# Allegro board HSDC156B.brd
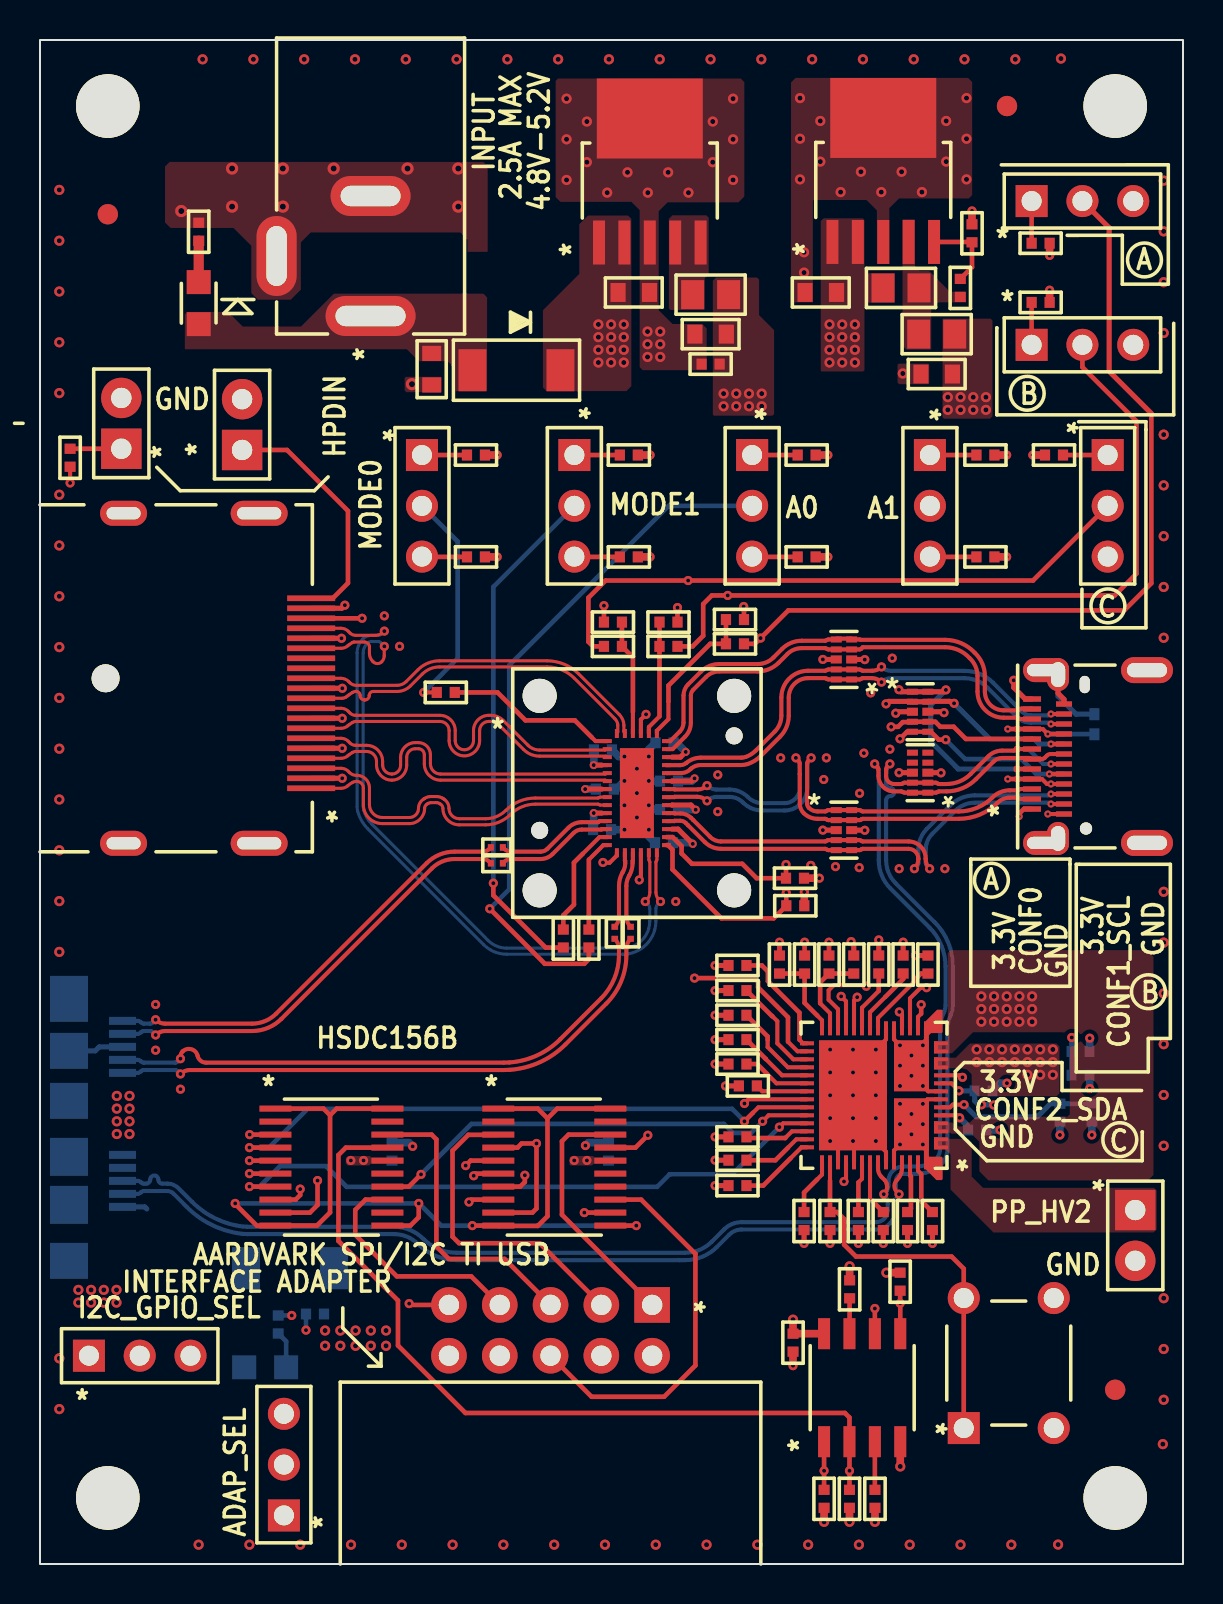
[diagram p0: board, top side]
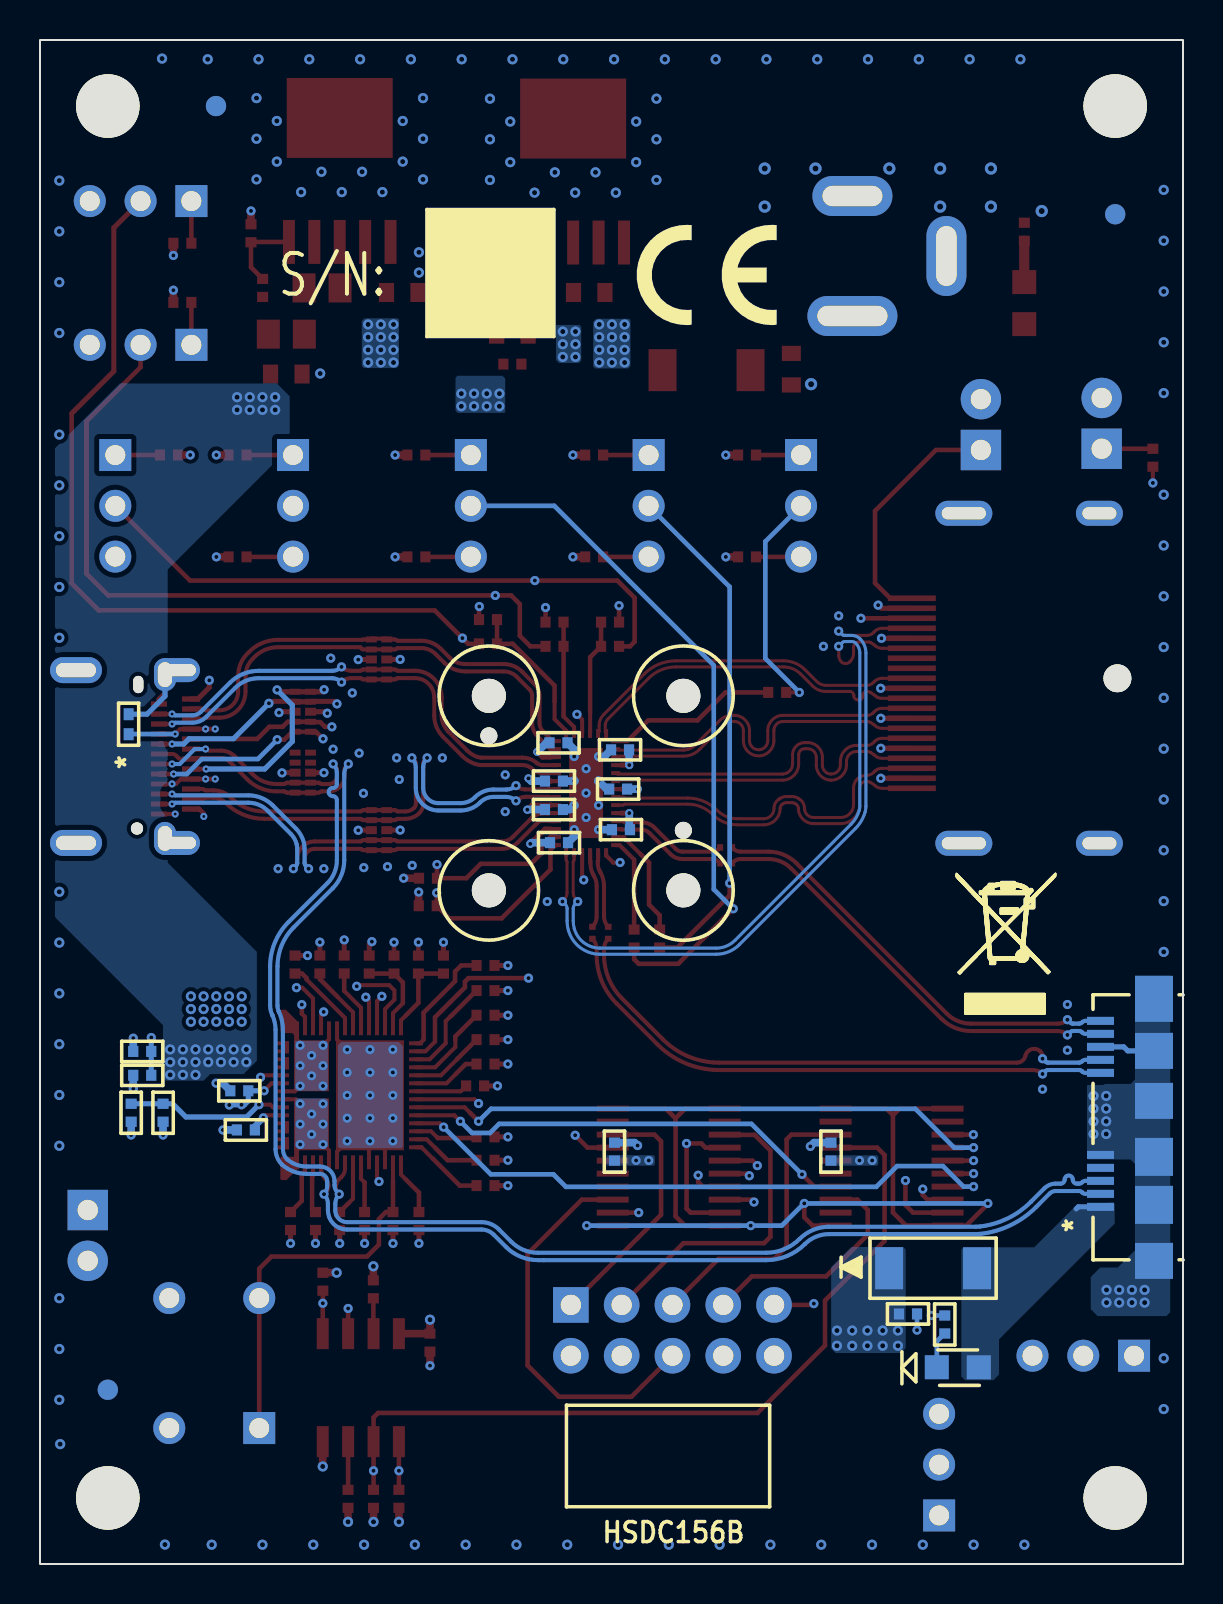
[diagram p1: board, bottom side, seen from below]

Outline 57.16 x 76.2 mm; copper layers: TOP, L2_GND, L3_PWR, L4_SIG, L5_GND, BOTTOM. Coordinates in mm from the lower left corner of the outline.
Outline path: rectangle 0,0 57.16,76.2

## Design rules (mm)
constraint set DEFAULT: min track width 0.229
net group AUX: nets AUXN AUXP
net group SSRXN: nets N16876304 SSRXN
net group SSRXP: nets N16876297 SSRXP
net group SSTXN: nets N16876344 SSTXN
net group SSTXP: nets N16876335 SSTXP

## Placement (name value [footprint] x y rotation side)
C1  0.33uF  [CAP_0201]  28.74 31.56 90 top
C2  0.33uF  [CAP_0201]  29.53 31.56 90 top
C3  0.33uF  [CAP_0201]  22.85 35.83 0 top
C4  0.33uF  [CAP_0201]  22.85 35.04 0 top
C5  0.1uF  [CAP_0402]  31.46 39.14 180 bottom
C6  0.1uF  [CAP_0402]  31.2 36.07 180 bottom
C7  0.1uF  [CAP_0402]  28.25 38.74 0 bottom
C8  0.1uF  [CAP_0402]  31.23 41.06 180 bottom
C9  0.1uF  [CAP_0402]  31.46 37.72 180 bottom
C10  0.1uF  [CAP_0402]  28.15 40.71 0 bottom
C11  0.1uF  [CAP_0402]  28.11 36.72 0 bottom
C12  10uF  [CAP_0402]  35.4 23.9 180 top
C13  100nF  [CAP_0402]  46.86 21.7 0 bottom
C14  10uF  [CAP_0402]  47.19 23.66 0 bottom
C15  .01uF  [CAP_0402]  37.66 11.07 270 top
C16  100nF  [CAP_0402]  28.43 20.62 90 bottom
C17  100nF  [CAP_0402]  17.6 20.62 90 bottom
C18  22uF  [CAP_0603]  29.69 63.58 0 top
C19  10uF  [CAP_0603]  33.54 61.49 180 top
C20  1uF  [CAP_0402]  33.54 60 180 top
C21  10uF  [CAP_0603]  39.04 63.58 180 top
C22  10uF  [CAP_0603]  44.84 59.5 180 top
C23  10uF  [CAP_0603]  19.59 59.74 270 top
C25  10uF  [CAP_0402]  13.75 12.5 180 bottom
D1  SCHOTTKY  [DIO_SOD-128]  12.5 14.79 180 bottom
D2  LED Green  [LED_SM_LTST-C170KGKT]  11.26 9.84 180 bottom
D3  TPD1E10B06  [DPY0002AA]  52.73 41.99 90 bottom
D4  SCHOTTKY  [DIO_SOD-128]  23.83 59.69 180 top
D5  LED Green  [LED_SM_LTST-C170KGKT]  7.94 63.04 270 top
J1  DC_PWR_JACK  [JACK_THRT_PJ-202AH]  16.53 62.4 90 top
JMP1  Header 2x1  [HDR_THVT_1X2_254_1097]  10.11 56.97 90 top
JMP2  Header 3x1  [HDR_THVT_1X3_254_550]  26.72 55.45 270 top
JMP3  Header 3x1  [HDR_THVT_1X3_254_550]  19.1 55.45 270 top
JMP4  Header 3x1  [HDR_THVT_1X3_254_550]  35.61 55.45 270 top
JMP5  Header 3x1  [HDR_THVT_1X3_254_550]  44.5 55.45 270 top
JMP6  Header 3x1  [HDR_THVT_1X3_254_550]  49.59 68.15 0 top
JMP7  Header 3x1  [HDR_THVT_1X3_254_550]  49.59 60.96 0 top
JMP8  Header 3x1  [HDR_THVT_1X3_254_550]  53.39 55.45 270 top
JMP9  Header 2x1  [HDR_THVT_1X2_254_1097]  4.07 57.03 90 top
JMP10  Header 2x1  [HDR_THVT_1X2_254_1097]  54.77 16.43 270 top
JMP11  Header 3x1  [HDR_THVT_1X3_254_550]  12.2 2.43 90 top
JMP12  Header 3x1  [HDR_THVT_1X3_254_550]  2.45 10.41 0 top
NOREF  -  []  0 0 0 top
NOREF#2  -  [unnamed#2]  3.39 3.3 90 top
NOREF#3  -  [unnamed#2]  48.36 72.9 270 top
NOREF#4  -  []  80.65 75.95 0 top
NOREF#5  -  [unnamed#2]  53.77 3.3 180 top
NOREF#6  -  [unnamed#2]  53.77 72.9 270 top
NOREF#7  -  []  0 76.2 0 top
NOREF#8  -  [unnamed#2]  3.39 72.9 0 top
NOREF#9  -  [unnamed#2]  53.77 8.71 180 top
NOREF#10  -  [unnamed#2]  3.39 67.49 0 top
NOREF#11  -  []  57.16 0 90 top
NOREF#12  -  []  -12.06 -32 0 top
NOREF#13  -  []  8.84 31.55 180 bottom
NOREF#14  -  []  23.82 64.45 180 bottom
NOREF#15  -  []  41.29 24.04 180 bottom
NOREF#16  -  []  44.8 64.55 180 bottom
NOREF#17  -  [unnamed#2]  48.36 72.9 90 bottom
NOREF#18  -  []  17.17 32.05 180 bottom
NOREF#19  -  [unnamed#2]  3.39 67.49 180 bottom
NOREF#20  -  [unnamed#2]  53.77 8.71 0 bottom
P1  JAE  DX07S024JJ2  [USB-C_SMRT_DX07S024JJ2]  52.31 40.37 90 top
P2  USB3_Micro_B  [USB-UB_SMRT_GSB343133]  1.8 22.13 90 bottom
P3  DP SINK-SIDE CONNECTOR  [DP_SMRT_472720001]  6.3 44.29 180 top
P4  Header 5x2 0.1" Shroud RA thru-hole  [CON_SHRD_THRT_30310-5002HB]  25.53 10.41 270 top
R1  0  [RES_0402]  28.65 45.88 0 top
R2  0 DNI  [RES_0402]  28.65 47.09 0 top
R3  0  [RES_0402]  34.75 46.01 0 top
R4  0 DNI  [RES_0402]  34.75 47.22 0 top
R5  0  [RES_0402]  31.43 45.88 0 top
R6  0 DNI  [RES_0402]  31.43 47.09 0 top
R7  2M  [RES_0402]  37.76 34.29 0 top
R8  2M  [RES_0402]  37.77 32.91 0 top
R9  330  [RES_0402]  11.91 11.98 90 bottom
R11  1k  [RES_0402]  47.28 55.45 180 top
R12  1k  [RES_0402]  29.45 55.45 180 top
R13  1k  [RES_0402]  38.34 55.45 180 top
R14  1k  [RES_0402]  21.8 55.45 180 top
R15  0  [RES_0402]  38.34 50.36 0 top
R16  0  [RES_0402]  47.28 50.36 0 top
R17  0  [RES_0402]  21.8 50.36 0 top
R18  0  [RES_0402]  29.45 50.36 0 top
R19  2k  [RES_0402]  50.71 55.45 0 top
R20  2k  [RES_0402]  50.04 63.08 180 top
R21  2k  [RES_0402]  50.04 66.04 180 top
R22  0  [RES_0402]  1.51 55.31 90 top
R30  0  [RES_0402]  20.29 43.58 0 top
R31  0  [RES_0402]  26.17 31.27 90 top
R32  0  [RES_0402]  27.45 31.27 90 top
R40  10k DNI  [RES_0402]  51 22.56 90 bottom
R41  10k DNI  [RES_0402]  52.04 24.43 180 bottom
R42  100k  [RES_0402]  42.17 17.15 270 top
R43  100k  [RES_0402]  44.63 17.15 90 top
R44  100k  [RES_0402]  40.93 17.15 270 top
R45  100  [RES_0402]  39.51 17.15 270 top
R46  100k  [RES_0402]  38.21 17.15 270 top
R47  100k  [RES_0402]  52.6 22.56 270 bottom
R48  100k  [RES_0402]  52.04 25.63 0 bottom
R49  100k  [RES_0402]  34.88 18.92 180 top
R50  100k  [RES_0402]  34.88 20.19 180 top
R51  100k  [RES_0402]  34.88 21.36 180 top
R52  10k  [RES_0402]  34.88 25 0 top
R53  3.3k  [RES_0402]  34.88 27.44 0 top
R54  3.3k  [RES_0402]  34.88 26.22 0 top
R55  100k  [RES_0402]  34.88 28.67 180 top
R56  10k  [RES_0402]  34.88 29.93 0 top
R57  3.3k  [RES_0402]  36.98 29.97 270 top
R58  3.3k  [RES_0402]  40.69 29.97 270 top
R59  0  [RES_0402]  38.24 29.97 90 top
R60  100k  [RES_0402]  44.4 29.97 90 top
R61  100k  [RES_0402]  43.16 29.97 90 top
R62  100k  [RES_0402]  41.94 29.97 90 top
R63  0  [RES_0402]  39.45 29.97 90 top
R64  3.3k  [RES_0402]  39.21 3.26 90 top
R65  3.3k  [RES_0402]  40.48 3.26 90 top
R66  3.3k DNI  [RES_0402]  43.01 14.12 270 top
R67  3.3k  [RES_0402]  41.75 3.26 270 top
R68  3.3k  [RES_0402]  40.49 13.73 270 top
R69  100k  [RES_0402]  43.38 17.15 90 top
R70  0  [RES_0805]  33.54 63.47 0 top
R71  0 DNI  [RES_0805]  43.06 63.8 0 top
R72  3.9k  [RES_0402]  46.02 63.8 90 top
R73  1.2k  [RES_0402]  46.61 66.54 90 top
R74  0  [RES_0805]  44.84 61.49 0 top
R75  330  [RES_0402]  7.94 66.61 90 top
SW1  B3F-1020  [SW_THVT_B3F-1020]  46.19 6.8 270 top
U1  TMUXHS4446  [SKT_IRONWOOD_C22569_2]  29.85 38.55 0 top
U2  TPD4E02B04  [DQA0010AA]  40.2 36.69 0 top
U3  TPD4E02B04  [DQA0010AA]  40.2 45.23 180 top
U4  TPD4E02B04  [DQA0010AA]  44.01 39.57 180 top
U5  TPD4E02B04  [DQA0010AA]  44.01 42.61 0 top
U6  TPS65987D  [RSH0056BA_MPAD]  41.71 23.43 180 top
U7  TMUX1134  [PW0020AA]  14.57 19.84 0 top
U8  TMUX1134  [PW0020AA]  25.72 19.84 0 top
U10  W25Q80  [SOIC_8_390X490_127]  41.11 8.82 90 top
U11  TPS7A4533  [DCQ0006AA]  30.49 69.17 90 top
U12  TPS7A4501  [DCQ0006AA]  42.17 69.2 90 top

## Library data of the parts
C1-C4 = cc0201: signal model: DEFAULT_CAPACITOR_330000pF_1_2
C5-C17 C20 C25 = cc0402
C18 C19 C21-C23 = cc0603
D1 D4 = SCHOTTKY
D2 D5 = LTST-C170KGKT
D3 = TPD1E10B06
J1 = 6140046600_DC_PWR_JACK
JMP1 JMP9 JMP10 = Header 2x1
JMP2-JMP8 JMP11 JMP12 = Header 3x1
P1 = TypeC_JAE_TopMNT_0
P2 = USB3_Micro_B_0
P3 = DP SINK-SIDE CONNECTOR_0
P4 = CONN PCB 5x2-S
R1-R9 R11-R22 R30-R32 R40-R69 R72 R73 R75 = r0402
R70 R71 R74 = r0805
SW1 = B3F-1020
U1 = TUSB1146_11
U2-U5 = TPD4E05U06
U6 = TPS65987D_1
U7 U8 = TMUX1134_0
U10 = W25Q80SSI
U11 = TPS79633KTT_2
U12 = TPS7A4501

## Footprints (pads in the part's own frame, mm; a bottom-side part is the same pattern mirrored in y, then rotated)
CAP_0201
  rect 0.3x0.33 smd: 1(-0.3,0) 2(0.3,0)
CAP_0402
  rect 0.51x0.55 smd: 1(-0.45,0) 2(0.45,0)
CAP_0603
  rect 0.76x0.95 smd: 1(-0.787,0) 2(0.787,0)
CON_SHRD_THRT_30310-5002HB
  rect 1.78x1.78 hole 1.016: 1(-2.54,5.08)
  round 1.78 hole 1.016: 2(0,5.08) 3(-2.54,2.54) 4(0,2.54) 5(-2.54,0) 6(0,0) 7(-2.54,-2.54) 8(0,-2.54) 9(-2.54,-5.08) 10(0,-5.08)
DCQ0006AA
  rect 2.2x0.6 smd: 1(-3.1,2.54) 2(-3.1,1.27) 3(-3.1,0) 4(-3.1,-1.27) 5(-3.1,-2.54)
  rect 4x5.3 smd: 6(3.1,0)
DIO_SOD-128
  rect 1.4x2.1 smd: 1(-2.2,0) 2(2.2,0)
DP_SMRT_472720001
  round 1.397 hole 1.397 unplated: (3.02,0)
  rect 2.4x0.28 smd: 1(-7.26,5.5) 2(-7.26,5) 3(-7.26,4.5) 4(-7.26,4) 5(-7.26,3.5) 6(-7.26,3) 7(-7.26,2.5) 8(-7.26,2) 9(-7.26,1.5) 10(-7.26,1) 11(-7.26,0.5) 12(-7.26,0) 13(-7.26,-0.5) 14(-7.26,-1) 15(-7.26,-1.5) 16(-7.26,-2) 17(-7.26,-2.5) 18(-7.26,-3) 19(-7.26,-3.5) 20(-7.26,-4)
  oval 2.85x1.25 hole 2.21x0.61: 21(-4.66,-8.25) 24(-4.66,8.25)
  oval 2.35x1.25 hole 1.702x0.61: 22(2.12,8.25) 23(2.12,-8.25)
DPY0002AA
  rect 0.6x0.5 smd: 1(-0.5,0) 2(0.5,0)
DQA0010AA
  rect 0.55x0.3 smd: 1(-0.385,1) 2(-0.385,0.5) 4(-0.385,-0.5) 5(-0.385,-1) 6(0.385,-1) 7(0.385,-0.5) 9(0.385,0.5) 10(0.385,1)
  rect 0.55x0.4 smd: 3(-0.385,0) 8(0.385,0)
HDR_THVT_1X2_254_1097
  rect 2.02x2.02 hole 1.016: 1(-1.27,0)
  round 2.02 hole 1.016: 2(1.27,0)
HDR_THVT_1X3_254_550
  rect 1.6x1.6 hole 1: 1(0,0)
  round 1.6 hole 1: 2(2.54,0) 3(5.08,0)
JACK_THRT_PJ-202AH
  oval 2x4.5 hole 1.016x3.505: 1(0,0)
  oval 2x4 hole 1.016x2.997: 2(6,0)
  oval 4x2 hole 2.997x1.016: 3(3,4.7)
LED_SM_LTST-C170KGKT
  rect 1.2x1.2 smd: 1(-1.05,0) 2(1.05,0)
PW0020AA
  rect 1.6x0.3 smd: 1(-2.8,2.925) 2(-2.8,2.275) 3(-2.8,1.625) 4(-2.8,0.975) 5(-2.8,0.325) 6(-2.8,-0.325) 7(-2.8,-0.975) 8(-2.8,-1.625) 9(-2.8,-2.275) 10(-2.8,-2.925) 11(2.8,-2.925) 12(2.8,-2.275) 13(2.8,-1.625) 14(2.8,-0.975) 15(2.8,-0.325) 16(2.8,0.325) 17(2.8,0.975) 18(2.8,1.625) 19(2.8,2.275) 20(2.8,2.925)
RES_0402
  rect 0.51x0.55 smd: 1(-0.45,0) 2(0.45,0)
RES_0805
  rect 1.15x1.45 smd: 1(-0.9,0) 2(0.9,0)
RSH0056BA_MPAD
  rect 0.7x0.2 smd: 1(-3.35,2.6) 2(-3.35,2.2) 3(-3.35,1.8) 4(-3.35,1.4) 5(-3.35,1) 6(-3.35,0.6) 7(-3.35,0.2) 8(-3.35,-0.2) 9(-3.35,-0.6) 10(-3.35,-1) 11(-3.35,-1.4) 12(-3.35,-1.8) 13(-3.35,-2.2) 14(-3.35,-2.6) 29(3.35,-2.6) 30(3.35,-2.2) 31(3.35,-1.8) 32(3.35,-1.4) 33(3.35,-1) 34(3.35,-0.6) 35(3.35,-0.2) 36(3.35,0.2) 37(3.35,0.6) 38(3.35,1) 39(3.35,1.4) 40(3.35,1.8) 41(3.35,2.2) 42(3.35,2.6)
  rect 0.2x0.7 smd: 15(-2.6,-3.35) 16(-2.2,-3.35) 17(-1.8,-3.35) 18(-1.4,-3.35) 19(-1,-3.35) 20(-0.6,-3.35) 21(-0.2,-3.35) 22(0.2,-3.35) 23(0.6,-3.35) 24(1,-3.35) 25(1.4,-3.35) 26(1.8,-3.35) 27(2.2,-3.35) 28(2.6,-3.35) 43(2.6,3.35) 44(2.2,3.35) 45(1.8,3.35) 46(1.4,3.35) 47(1,3.35) 48(0.6,3.35) 49(0.2,3.35) 50(-0.2,3.35) 51(-0.6,3.35) 52(-1,3.35) 53(-1.4,3.35) 54(-1.8,3.35) 55(-2.2,3.35) 56(-2.6,3.35)
  rect 1.75x2.6 smd: 57(-1.875,1.45)
  rect 1.75x2.55 smd: 58(-1.875,-1.475)
  rect 3.4x5.5 smd: 59(1.05,0)
SKT_IRONWOOD_C22569_2
  round 1.702 hole 1.702 unplated: (-4.863,4.863) (-4.863,-4.863) (4.863,4.863) (4.863,-4.863)
  round 0.85 hole 0.85 unplated: (-4.863,-1.863) (4.863,2.863)
  rect 0.45x0.2 smd: 1(-1.48,2.6) 2(-1.48,2.2) 3(-1.48,1.8) 4(-1.48,1.4) 5(-1.48,1) 6(-1.48,0.6) 7(-1.48,0.2) 8(-1.48,-0.2) 9(-1.48,-0.6) 10(-1.48,-1) 11(-1.48,-1.4) 12(-1.48,-1.8) 13(-1.48,-2.2) 14(-1.48,-2.6) 21(1.48,-2.6) 22(1.48,-2.2) 23(1.48,-1.8) 24(1.48,-1.4) 25(1.48,-1) 26(1.48,-0.6) 27(1.48,-0.2) 28(1.48,0.2) 29(1.48,0.6) 30(1.48,1) 31(1.48,1.4) 32(1.48,1.8) 33(1.48,2.2) 34(1.48,2.6)
  rect 0.2x0.45 smd: 15(-1,-2.98) 16(-0.6,-2.98) 17(-0.2,-2.98) 18(0.2,-2.98) 19(0.6,-2.98) 20(1,-2.98) 35(1,2.98) 36(0.6,2.98) 37(0.2,2.98) 38(-0.2,2.98) 39(-0.6,2.98) 40(-1,2.98)
  rect 1.7x4.5 smd: 41(0,0)
SOIC_8_390X490_127
  rect 1.55x0.6 smd: 1(-2.7,1.905) 2(-2.7,0.635) 3(-2.7,-0.635) 4(-2.7,-1.905) 5(2.7,-1.905) 6(2.7,-0.635) 7(2.7,0.635) 8(2.7,1.905)
SW_THVT_B3F-1020
  rect 1.6x1.6 hole 1: 1(0,0)
  round 1.6 hole 1: 2(-6.5,0) 3(0,4.5) 4(-6.5,4.5)
unnamed#2
  round 3.175 hole 3.175 unplated: (0,0)
USB-C_SMRT_DX07S024JJ2
  round 0.61 hole 0.61 unplated: (-3.6,0)
  oval 0.864x0.508 hole 0.864x0.508 unplated: (3.6,0.065)
  oval 1.65x1.1 hole 1.245x0.711: 1(-4.095,1.4) 5(4.095,1.4)
  oval 1.2x2.3 hole 0.61x1.905: 2(-4.32,2) 6(4.32,2)
  oval 1.3x2.6 hole 0.711x2.007: 3(-4.32,-3.05) 4(4.32,-3.05)
  rect 0.27x0.9 smd: A1(-2.625,2.7) A2(-2.125,2.7) A3(-1.625,2.7) A4(-1.125,2.7) A5(-0.625,2.7) A6(-0.125,2.7) A7(0.375,2.7) A8(0.875,2.7) A9(1.375,2.7) A10(1.875,2.7) A11(2.375,2.7) A12(2.875,2.7)
  rect 0.27x0.8 smd: B1(2.625,1.1) B2(2.125,1.1) B3(1.625,1.1) B4(1.125,1.1) B5(0.625,1.1) B6(0.125,1.1) B7(-0.375,1.1) B8(-0.875,1.1) B9(-1.375,1.1) B10(-1.875,1.1) B11(-2.375,1.1) B12(-2.875,1.1)
USB-UB_SMRT_GSB343133
  rect 0.4x1.35 smd: 1(-4.275,2.325) 2(-3.625,2.325) 3(-2.975,2.325) 4(-2.325,2.325) 5(-1.675,2.325) 6(2.425,2.325) 7(3.075,2.325) 8(3.725,2.325) 9(4.375,2.325) 10(5.025,2.325)
  rect 1.8x1.9 smd: 11(-6.975,-0.35) 14(1.025,-0.35) 15(3.525,-0.35)
  rect 1.9x1.9 smd: 12(-4.175,-0.35) 13(-1.775,-0.35)
  rect 2.3x1.9 smd: 16(6.125,-0.35)

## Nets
3.3V: C5.1 C6.1 C7.1 C8.1 C9.1 C10.1 C11.1 C13.1 C19.1 C20.1 JMP1.2 R11.1 R12.1 R13.1 R14.1 R19.1 R20.1 R21.1 R70.2 U1.4 U1.7 U1.10 U1.23 U1.26 U1.29 U1.32(VCC7) U6.5(VIN_3V3)
5V: C22.1 R74.2 U6.11 U6.12 U6.25
GND: C5.2 C6.2 C7.2 C8.2 C9.2 C10.2 C11.2 C12.2 C13.2 C14.2 C15.2 C16.2 C17.2 C18.2 C19.2 C20.2 C21.2 C22.2 C23.2 C25.2 D3.2 J1.2 J1.3(GND#3) JMP6.3 JMP7.3 JMP8.3 JMP9.2 JMP10.2 JMP11.3 JMP12.3 P1.1 P1.2 P1.3 P1.4 P1.5 P1.6 P1.A1 P1.A12 P1.B1 P1.B12 P2.5 P2.8 P2.11 P2.12 P2.13 P2.14 P2.15 P2.16 P3.2 P3.5 P3.8 P3.11 P3.16 P3.19 P3.21 P3.22 P3.23 P3.24(SHLD#24) P4.2 R7.2 R8.2 R9.2 R15.2 R16.2 R17.2 R18.2 R42.2 R43.1 R44.2 R45.2 R46.2 R47.2 R48.2 R49.2 R50.2 R51.2 R55.2 R60.2 R61.2 R62.2 R69.1 R73.2 R75.2 U1.15 U1.18 U1.37 U1.41 U2.3 U2.8 U3.3 U3.8 U4.3 U4.8 U5.3 U5.8 U6.20 U6.45 U6.46 U6.47 U6.51 U6.59 U7.5(VSS) U7.6 U8.5(VSS) U8.6 U8.7 U8.12 U10.4 U11.3 U11.6 U12.3 U12.6
GND_NC: P4.6 U8.13
VBUS_C: D3.1 P1.A4 P1.A9 P1.B4 P1.B9(VBUS#B9) U6.3 U6.4 U6.13 U6.14
VBUS_IN: D1.2 D2.2 P2.1(VBUS)
A0: JMP4.2 R32.1
A1: JMP5.2 R4.2
ADAP_SEL: JMP11.2 U7.1 U7.10 U7.11 U7.20 U8.1 U8.10 U8.11 U8.20
ADCIN1: R40.2 R47.1 U6.6
ADCIN2: R41.2 R48.1 U6.10
AUXN: P3.17 U1.20
AUXP: P3.15 U1.19
CC1: P1.A5 U5.1 U5.10 U6.24
CC2: P1.B5 U5.2 U5.9(NC9) U6.26
CLK: P4.7 U7.13
CONF0: JMP6.2 R3.2 U6.18
CONF1: JMP7.2 R5.2 U6.17
CONF2: JMP8.2 R1.1 U6.16
DM: P1.A7 P1.B7 P2.2 U4.2 U4.9(NC9) U6.53
DP: P1.A6 P1.B6 P2.3 U4.1 U4.10 U6.50
DP0N: P3.10 U1.40
DP0P: P3.12 U1.39
DP1N: P3.7 U1.3
DP1P: P3.9 U1.2
DP2N: P3.4 U1.6
DP2P: P3.6 U1.5
DP3N: P3.1 U1.9
DP3P: P3.3 U1.8
HPDIN: P3.18 R22.1 U6.30
I2C2_SCL: R53.2 U6.32
I2C2_SDA: R54.2 U6.33
I2C_GPIO_SEL: JMP12.2
LDO_3V3: C14.1 C15.1 R40.1 R41.1 R52.1 R53.1 R54.1 R56.1 R57.1 R58.1 R64.1 R65.1 R66.1 R67.2 R68.1 SW1.3 SW1.4 U6.9 U10.8(VCC)
MISO: P4.5 U7.18
MODE0: JMP3.2 R30.1
MODE1: JMP2.2 R31.1
MOSI: P4.8(9) U7.3
MUX_SCL: R6.2 R63.2 U7.9 U8.17
MUX_SDA: R2.1 R59.2 U8.4 U8.9
PAD1: U6.8 U6.15 U6.19 U6.58
PAD2: U6.7 U6.52 U6.56 U6.57
RX1N: P1.B10 U1.24 U2.5 U2.6
RX1P: P1.B11 U1.25 U2.4 U2.7
RX2N: P1.A10 U1.33 U3.4 U3.7
RX2P: P1.A11 U1.34 U3.5 U3.6
SBU1: P1.A8 R7.1 U1.22 U5.4 U5.7
SBU2: P1.B8 R8.1 U1.21 U5.5 U5.6
SCL: P4.1 U8.18
SDA: P4.3 U8.3
SDA_GND: P4.10 U8.8
SPI_CLK: U6.38 U7.14 U10.6
SPI_MISO: R65.2 U6.36 U7.17 U10.2
SPI_MOSI: R66.2 U6.37 U7.4 U10.5
SPI_SS: R64.2 U6.39 U7.7 U10.1
SS: P4.9 U7.8
SSRXN: C4.1 P2.9
SSRXP: C3.1 P2.10
SSTXN: C1.1 P2.7
SSTXP: C2.1 P2.6
SYS_5V: C16.1 C17.1 C18.1 C21.1 C25.1 D1.1(K) D4.1(K) JMP11.1 JMP12.1 R71.1 U7.16 U8.16 U11.1(SHDN/) U11.2 U12.1(SHDN/) U12.2
TX1N: P1.A3 U1.27 U2.1 U2.10
TX1P: P1.A2 U1.28 U2.2 U2.9(NC9)
TX2N: P1.B3 U1.30 U3.1 U3.10
TX2P: P1.B2 U1.31 U3.2 U3.9(NC9)
N16768147: D2.1(CATHODE) R9.1
N16769233: JMP1.1 P3.20
N16769682: R5.1 R6.1 U1.36
N16769693: R3.1 R4.1 U1.35
N16786555: JMP4.1 R13.2
N16786563: JMP4.3 R15.1
N16786728: JMP3.1 R14.2
N16786746: JMP3.3 R17.1
N16786904: JMP2.1 R12.2
N16786924: JMP2.3 R18.1
N16791273: JMP10.1 U6.1 U6.2
N16791721: R60.1 U6.21
N16791724: R61.1 U6.22
N16791727: R62.1 U6.23
N16791992: R58.2 R63.1 U6.27
N16792053: R57.2 R59.1 U6.28
N16792062: R56.2 U6.29
N16792248: R55.1 U6.31
N16792431: R52.2 U6.34
N16792503: C12.1 U6.35
N16792701: R51.1 U6.40
N16792704: R50.1 U6.41
N16792707: R49.1 U6.42
N16792812: R46.1 U6.43
N16792872: R45.1 SW1.1 SW1.2 U6.44
N16793299: R44.1 U6.48
N16793302: R42.1 U6.49
N16793739: R69.2 U6.54
N16793744: R43.2 U6.55
N16794056: R68.2 U10.7
N16794233: R67.1 U10.3
N16795663: R70.1 U11.4 U11.5
N16795996: R71.2 R72.1 R74.1 U12.4
N16796118: R72.2 R73.1 U12.5
N16796371: C23.1 D4.2 D5.2 J1.1
N16796449: D5.1(CATHODE) R75.1
N16804565: JMP9.1 R22.2
N16876297: C3.2 U1.11
N16876304: C4.2 U1.12
N16876335: C2.2 U1.17
N16876344: C1.2 U1.16
N16883926: JMP6.1 R21.2
N16883933: JMP7.1 R20.2
N16883940: JMP8.1 R19.2
N16885672: R1.2 R2.2 U1.38
N16894778: JMP5.1 R11.2
N16894795: JMP5.3 R16.1
N16919722: R31.2 U1.13
N16919741: R32.2 U1.14
N16919748: R30.2 U1.1

Pads without a net: P2 4; P3 13 14; P4 4; U4 4 5 6 7; U7 2 12 15 19; U8 2 14 15 19

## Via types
v1: diameter 0.457, hole 0.203, TOP to BOTTOM, 215 vias
v2: diameter 0.356, hole 0.152, TOP to BOTTOM, 17 vias
v3: diameter 0.508, hole 0.254, TOP to BOTTOM, 216 vias
v4: diameter 0.406, hole 0.203, TOP to BOTTOM, 7 vias
v5: diameter 0.61, hole 0.305, TOP to BOTTOM, 10 vias

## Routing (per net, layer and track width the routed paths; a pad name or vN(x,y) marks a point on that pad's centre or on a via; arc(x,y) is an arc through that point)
3.3V: length 19.9
  TOP w0.203: 31.61,39.14 U1.29 ; v1(45.99,22.31) 45.86,22.43 U6.5 ; 31.61,37.95 U1.26 ; 31.61,36.74 U1.23 ; U1.10 28.09,37.55 ; 31.61,40.35 U1.32 ; U1.4 28.09,39.95 ; U1.7 28.09,38.74
  TOP w0.254: v4(32.29,40.61) 32.03,40.35 31.61,40.35 ; 31.61,39.14 31.61,39.15 32.6,39.15 v4(32.73,39.28) ; v4(32.64,36.01) 31.9,36.74 31.61,36.74 ; 28.09,39.95 v4(27.69,39.95) ; 31.61,37.95 31.61,37.95 32.56,37.95 v4(32.79,37.71) ; v4(27.69,37.55) 27.73,37.55 27.73,37.55 28.09,37.55 ; 28.09,38.74 v4(27.26,38.74)
  TOP w0.381: R21.1 v1(50.49,65.43) ; R12.1 v1(30.51,55.45) ; R14.1 v1(22.86,55.45) ; R13.1 v1(39.4,55.45) ; R19.1 v1(49.65,55.45) ; R11.1 v1(48.34,55.45) ; R20.1 v1(50.49,63.69)
  BOTTOM w0.305: C13.1 46.41,21.89 v1(45.99,22.31)
  BOTTOM w0.381: v4(27.69,39.95) 27.7,39.96 C10.1 ; C11.1 27.69,36.75 v4(27.69,37.55) ; v4(32.79,37.71) 32.78,37.72 C9.1 ; v4(32.73,39.28) 32.59,39.14 C5.1 ; C6.1 32.58,36.07 v4(32.64,36.01) ; C8.1 31.83,41.06 v4(32.29,40.61) ; C7.1 v4(27.26,38.74)
  vias: v3(34.18,58.52) v3(34.18,57.88) v3(34.82,58.52) v3(34.82,57.88) v3(35.45,58.52) v3(35.45,57.88) v3(36.09,58.52) v3(36.09,57.88)
5V: length 1.7
  TOP w0.203: U6.25 40.31,28.14 v1(40.06,28.38)
  vias: v3(45.4,58.34) v3(45.4,57.71) v3(46.03,58.34) v3(46.03,57.71) v3(46.67,58.34) v3(46.67,57.71) v3(46.84,25.73) v3(46.84,25.09) v3(47.3,58.34) v3(47.3,57.71) v3(47.47,25.73) v3(47.47,25.09) v3(48.11,25.73) v3(48.11,25.09) v3(48.74,25.73) v3(48.74,25.09) v3(49.38,25.73) v3(49.38,25.09) v3(49.38,24.46) v3(50.01,25.73) v3(50.01,25.09) v3(50.01,24.46) v3(50.65,25.73) v3(50.65,25.09) v3(50.65,24.46)
GND: length 71.6
  TOP w0.203: v1(30.31,42.48) 30.05,42.22 U1.37 ; U6.20 42.31,26.23 v1(41.8,25.72) 41.8,25.74 ; U1.18 30.05,34.29 v1(29.97,34.2) ; U6.45 39.91,20.76 v1(39.51,21.15) ; v1(40.2,19.12) 40.31,19.23 U6.46 ; U1.15 28.85,35.43 28.48,35.06 28.17,35.06 v1(28.15,35.08) ; v1(40.66,21.15) 40.71,21.1 U6.47 ; v2(50.4,37.5) P1.B12 ; 40.71,23.38 v1(40.66,23.43) ; U6.51 42.31,20.61 41.8,21.12 v1(41.8,21.15)
  TOP w0.229: v1(24.24,19.44) 24.24,19.1 24.02,18.87 U8.7 ; P1.A1 49.19,37.75 48.97,37.52 v2(48.97,37.38) ; U8.6 21.79,19.52 v1(21.69,19.41) ; U8.5 21.54,20.17 v1(21.29,19.92) ; U7.5 v1(10.47,20.17) ; U8.12 v1(27.22,17.57) ; U7.6 v1(10.47,19.52)
  TOP w0.254: U2.3 v1(39.15,36.69) ; R69.1 v1(43.38,16.03) ; P1.B1 51.21,43.23 50.91,43.53 P1.5 ; P3.8 v1(15.11,42.29) ; P3.5 v1(15.11,40.79) ; P3.2 v1(15.11,39.29) ; U2.8 41.22,36.69 arc(41.24,36.69) v1(41.24,36.69) ; R42.2 v1(42.17,16.03) ; R44.2 v1(40.93,16.03) ; R46.2 v1(38.21,16.03) ; R61.2 v1(43.16,31.09) ; R62.2 v1(41.94,31.2) ; U4.3 45.04,39.57 arc(45.05,39.56) v1(45.05,39.56) ; U3.3 41.22,45.23 arc(41.24,45.23) v1(41.24,45.22) ; R55.2 v1(33.76,28.67) ; R43.1 v1(44.63,16.03) ; v1(48.69,44.19) 48.69,43.83 49.27,43.25 P1.A12 ; R51.2 v1(33.76,21.36) ; R49.2 v1(33.76,18.92) ; v1(45.21,42.57) 45.16,42.61 U5.8 ; P3.19 15.09,47.79 v1(15.25,47.94) ; U4.8 v1(42.96,39.57) ; R45.2 v1(39.51,16.03) ; v1(42.79,42.54) 42.87,42.61 U5.3 ; U3.8 v1(39.15,45.23) ; R60.2 v1(43.78,30.42) ; P3.11 v1(15.12,43.79) ; C12.2 v1(34.28,23.9) ; R50.2 v1(33.76,20.19) ; P3.16 v1(15.08,46.29)
  TOP w0.381: R8.2 v1(38.22,33.6) ; R15.2 v1(39.4,50.36) ; R16.2 v1(48.34,50.36) ; R18.2 v1(30.51,50.36) ; R17.2 v1(22.86,50.36) ; U10.4 v3(43.02,4.88) ; C15.2 v1(37.66,9.92) ; R73.2 v1(46.61,67.65) ; R7.2 v1(38.97,34.29)
  BOTTOM w0.229: C25.2 v1(13.3,11.69) ; R9.2 v1(12.59,12.43)
  BOTTOM w0.254: P2.15 2.76,25.66 2.96,25.86 P2.8 ; P1.5 50.91,43.39 51.81,42.49 D3.2
  BOTTOM w0.381: C13.2 v1(48.01,21.7) ; v1(30.45,39.15) 30.46,39.14 C5.2 ; R48.2 v1(52.49,26.29) ; C16.2 27.42,21.07 v1(27.27,20.92) ; v1(48.35,24.04) 48.02,24.04 C14.2 ; C6.2 30.45,36.38 v1(30.45,36.72) ; C8.2 30.45,40.73 v1(30.45,40.37) ; C10.2 28.94,40.37 v1(29.23,40.37) ; C9.2 30.66,37.72 v1(30.45,37.94) ; v1(18.64,20.88) 18.45,21.07 C17.2 ; R47.2 v1(52.6,21.45) ; v1(29.23,39.15) 28.82,38.74 C7.2 ; C11.2 v1(29.23,36.72)
  vias: v1(5.78,27.98) v1(5.78,25.69) v1(7.02,23.74) v1(17.22,47.41) v1(17.98,45.88) v1(29.23,37.94) v1(29.85,39.76) v1(29.85,38.55) v1(29.85,37.33) v1(31.79,33.12) v1(33.89,39.46) v1(33.89,37.62) v1(37.04,40.31) v1(38.55,34.93) v1(39.19,39.23) v1(39.32,40.31) v1(39.51,25.72) v1(39.51,24.58) v1(39.51,23.43) v1(39.51,22.29) v1(39.78,34.87) v1(40.66,25.72) v1(40.66,24.58) v1(40.66,22.29) v1(40.98,38.54) v1(40.97,34.82) v1(41.2,40.54) v1(41.54,43.55) v1(41.8,24.58) v1(41.8,23.43) v1(41.8,22.29) v1(42.5,40.74) v1(42.62,45.29) v1(42.96,34.77) v1(45.25,34.77) v3(0.97,68.71) v3(0.97,66.17) v3(0.97,63.63) v3(0.97,61.09) v3(0.97,58.55) v3(0.97,53.47) v3(0.97,50.93) v3(0.97,48.39) v3(0.97,45.85) v3(0.97,43.31) v3(0.97,40.77) v3(0.97,38.23) v3(0.97,35.69) v3(0.97,33.15) v3(0.97,30.61) v3(0.97,10.29) v3(0.97,7.75) v3(1.92,13.71) v3(1.92,13.07) v3(2.55,13.71) v3(2.55,13.07) v3(3.19,13.71) v3(3.19,13.07) v3(3.84,23.4) v3(3.84,22.77) v3(3.84,22.13) v3(3.84,21.5) v3(3.82,13.71) v3(3.82,13.07) v3(4.48,23.4) v3(4.48,22.77) v3(4.48,22.13) v3(4.48,21.5) v3(7.93,0.97) v3(8.13,75.23) v3(10.47,0.97) v3(10.67,75.23) v3(13.01,0.97) v3(13.21,75.23) v3(15.55,0.97) v3(15.75,75.23) v3(18.09,0.97) v3(18.29,75.23) v3(20.63,0.97) v3(20.83,75.23) v3(23.17,0.97) v3(23.37,75.23) v3(25.71,0.97) v3(25.91,75.23) v3(26.33,73.27) v3(26.33,71.23) v3(26.33,69.2) v3(27.35,72.12) v3(27.35,70.09) v3(28.25,0.97) v3(28.36,68.57) v3(28.45,75.23) v3(29.38,69.58) v3(30.39,68.57) v3(30.38,61.62) v3(30.38,60.99) v3(30.38,60.35) v3(30.79,0.97) v3(30.99,75.23) v3(31.02,61.62) v3(31.02,60.99) v3(31.02,60.35) v3(31.41,69.58) v3(32.43,68.57) v3(33.33,0.97) v3(33.53,75.23) v3(33.64,72.12) v3(33.64,70.09) v3(34.66,73.27) v3(34.66,71.23) v3(34.66,69.2) v3(35.87,0.97) v3(36.07,75.23) v3(38,73.29) v3(38,71.26) v3(38,69.23) v3(38.21,65.59) v3(38.21,64.57) v3(38.41,0.97) v3(38.61,75.23) v3(39.02,72.15) v3(39.02,70.12) v3(40.04,68.6) v3(40.95,0.97) v3(41.05,69.61) v3(41.15,75.23) v3(42.07,68.6) v3(43.08,69.61) v3(43.15,59.52) v3(43.49,0.97) v3(43.69,75.23) v3(44.1,68.6) v3(45.32,72.15) v3(45.32,70.12) v3(46.03,0.97) v3(46.23,75.23) v3(46.33,73.29) v3(46.33,71.26) v3(46.33,69.23) v3(48.57,0.97) v3(48.77,75.23) v3(50.91,0.97) v3(51.05,75.27) v3(56.15,5.99) v3(56.19,69.17) v3(56.19,66.63) v3(56.19,64.09) v3(56.19,61.55) v3(56.19,56.47) v3(56.19,53.93) v3(56.19,51.39) v3(56.19,48.85) v3(56.19,46.31) v3(56.19,33.61) v3(56.19,31.07) v3(56.19,28.53) v3(56.19,25.99) v3(56.19,23.45) v3(56.19,20.91) v3(56.19,13.29) v3(56.19,10.75) v3(56.19,8.21) v5(7.07,67.65) v5(9.61,69.77) v5(9.61,67.87) v5(12.15,69.77) v5(12.15,67.87) v5(14.69,69.77) v5(18.38,69.77) v5(18.6,58.99) v5(20.92,69.77) v5(20.92,67.87)
GND_NC: length 19.7
  TOP w0.229: P4.6 27.58,8.36 31.21,8.36 32.78,9.93 32.78,15.5 30.06,18.22 U8.13
VBUS_C: length 8.2
  TOP w0.203: v2(50.4,41.5) 50.15,41.75 P1.A9 ; P1.A4 50.11,39.25 50.35,39 v2(50.55,39) 50.56,39 P1.B9
  TOP w0.229: P1.A4 v2(48.88,39.25) v2(48.39,39.25) ; v2(50.4,41.5) P1.B4 ; v2(48.39,41.75) v2(48.88,41.75) P1.A9
  BOTTOM w0.229: D3.1 52.72,41.5 v2(50.4,41.5)
  vias: v3(47.07,28.38) v3(47.07,27.75) v3(47.07,27.11) v3(47.71,28.38) v3(47.71,27.75) v3(47.71,27.11) v3(48.34,28.38) v3(48.34,27.75) v3(48.34,27.11) v3(48.98,28.38) v3(48.98,27.75) v3(48.98,27.11) v3(49.61,28.38) v3(49.61,27.75) v3(49.61,27.11)
VBUS_IN: length 1.3
  BOTTOM w0.254: P2.1 5.24,17.86 5.34,17.75
A0: length 34.8
  TOP w0.229: v1(22.49,32.76) 25.24,30.01 27.22,30.01 27.45,30.24 R32.1
  BOTTOM w0.229: v1(22.49,32.76) 23.46,33.73 23.46,44.93 31.44,52.91 JMP4.2
A1: length 12.1
  TOP w0.203: 35.2,47.86 v1(35.19,47.87)
  TOP w0.229: R4.2 35.2,47.86
  L4_SIG w0.152: JMP5.2 39.47,47.87 v1(35.19,47.87)
ADAP_SEL: length 69.4
  TOP w0.229: 14.5,22.44 14.5,17.58 13.85,16.93 11.78,16.93 U7.10 10.84,16.92 9.76,18 v1(9.76,18.03) ; 14.5,22.44 14.83,22.77 U7.20 ; 14.5,22.44 14.18,22.77 U7.1 ; 25.38,22.28 25.87,22.77 U8.20 ; 25.38,22.28 25.38,17.39 24.89,16.9 22.93,16.9 U8.10 v1(21.62,16.92) ; 25.38,22.28 24.89,22.77 U8.1 ; v1(18.94,18.03) 18.94,17.34 18.52,16.92 U7.11 ; U8.11 v1(29.82,16.92)
  L4_SIG w0.152: JMP11.2 10.47,6.69 10.47,17.29 9.76,18 v1(9.76,18.03)
  BOTTOM w0.229: v1(29.82,16.92) v1(21.62,16.92) 20.06,16.92 18.95,18.03 v1(18.94,18.03) v1(9.76,18.03)
ADCIN1: length 8.1
  TOP w0.203: v1(46.21,22.97) 45.64,22.97 45.51,22.83 U6.6
  BOTTOM w0.254: R47.1 R40.2 50.52,23.01 49.86,22.35 46.82,22.35 v1(46.21,22.97)
ADCIN2: length 10.4
  TOP w0.203: U6.10 46.03,24.43 v1(46.13,24.33)
  L4_SIG w0.254: v1(51.59,26.33) 50.97,26.33 50.87,26.43 46.47,26.43 46.13,26.09 v1(46.13,24.33)
  BOTTOM w0.254: v1(51.59,26.33) R48.1 R41.2
AUXN: length 36.2
  TOP w0.152: v1(17.22,46.64) 17.18,46.6 arc(16.99,46.48) 16.77,46.43 15.79,46.43 arc(15.63,46.46) 15.5,46.55 15.41,46.64 arc(15.25,46.75) 15.06,46.79 P3.17 ; v1(31.03,33.12) 30.96,33.19 arc(30.84,33.37) 30.8,33.58 30.8,35.1 arc(30.81,35.13) 30.82,35.16 arc(30.84,35.18) 30.85,35.22 U1.20
  BOTTOM w0.152: v1(31.03,33.12) 30.89,32.98 arc(30.82,32.88) 30.8,32.77 30.8,32.15 arc(30.78,31.92) 30.73,31.68 arc(30.14,30.82) 29.15,30.49 23.34,30.49 arc(22.72,30.61) 22.19,30.97 16.39,36.77 arc(16.09,37.15) 15.9,37.6 arc(15.87,37.74) 15.86,37.88 15.86,45.55 arc(15.93,45.93) 16.15,46.26 arc(16.34,46.38) 16.56,46.43 16.94,46.43 arc(17,46.44) 17.05,46.47 v1(17.22,46.64)
AUXP: length 36.2
  TOP w0.152: v1(30.27,33.12) 30.34,33.19 arc(30.45,33.37) 30.5,33.58 30.5,35.1 arc(30.49,35.13) 30.47,35.16 arc(30.46,35.18) 30.45,35.21 U1.19 ; v1(17.22,45.88) 17.21,45.87 17.21,45.42 arc(17.18,45.25) 17.09,45.11 arc(16.87,45.02) 16.66,45.11 16.64,45.14 arc(16.52,45.32) 16.47,45.53 16.47,45.85 arc(16.4,46.03) 16.22,46.1 15.71,46.1 arc(15.66,46.09) 15.62,46.07 arc(15.54,46.02) 15.46,45.97 arc(15.42,45.94) 15.39,45.91 arc(15.23,45.82) 15.06,45.79 P3.15
  BOTTOM w0.152: v1(17.22,45.88) 17.01,46.09 arc(16.97,46.12) 16.93,46.12 16.56,46.12 arc(16.46,46.1) 16.37,46.04 arc(16.21,45.82) 16.16,45.55 16.16,37.88 arc(16.17,37.78) 16.19,37.69 arc(16.35,37.31) 16.6,36.98 22.4,31.18 arc(22.83,30.89) 23.34,30.79 29.15,30.79 arc(29.96,31.06) 30.44,31.77 arc(30.48,31.96) 30.49,32.15 30.49,32.77 arc(30.47,32.89) 30.4,32.99 v1(30.27,33.12)
CC1: length 37.4
  TOP w0.203: U6.24 40.71,28.18 v1(40.86,28.34)
  TOP w0.229: P1.A5 v2(48.85,39.75)
  TOP w0.254: v1(45.3,43.71) 45.21,43.61 U5.10 U5.1 43.05,43.61 v1(42.95,43.72)
  L4_SIG w0.254: v1(42.95,43.72) 43.83,43.72 44.56,42.98 44.56,40.96 45.77,39.75 45.77,36.13 46.32,35.58 46.32,27.59 45.29,26.55 42.34,26.55 41.79,27.1 41.79,27.42 v1(40.86,28.34)
  BOTTOM w0.254: v1(45.3,43.71) 44.54,42.95 44.54,41.13 45.92,39.75 v2(48.85,39.75)
CC2: length 37.1
  TOP w0.203: v1(41.32,28.89) 41.26,28.94 39.7,28.94 39.44,28.68 39.44,28.21 39.91,27.74 U6.26
  TOP w0.229: v2(50.55,41) P1.B5
  TOP w0.254: v1(42.31,43.01) 42.43,43.13 43.61,43.13 U5.2 U5.9 44.42,43.13 45.47,43.13 arc(45.6,43.11) v1(45.71,43.03)
  L4_SIG w0.254: v1(42.31,43.01) 42.43,43.13 43.3,43.13 43.9,42.53 43.9,36.99 45.82,35.08 45.82,28 44.83,27.01 42.7,27.01 42.31,27.4 42.31,27.89 v1(41.32,28.89)
  BOTTOM w0.254: v2(50.55,41) 49.97,41 49.7,41.26 47.48,41.26 v1(45.71,43.03)
CLK: length 11.7
  TOP w0.229: U7.13 16.28,18.22 15.77,17.71 15.77,16.46 17.85,14.38 21.56,14.38 P4.7
CONF0: length 71.2
  TOP w0.203: v1(42.97,27.61) 43.11,27.47 U6.18
  TOP w0.229: 55.57,57.53 55.57,49.04 54.22,47.68 37.42,47.68 v1(36.03,46.29) 35.75,46.01 R3.2
  TOP w0.254: JMP6.2 53.47,66.81 53.47,59.64 55.57,57.53
  L4_SIG w0.152: v1(42.97,27.61) 43.12,27.45 44.57,27.45 45.36,28.24 45.36,29.05 44.34,30.08 44.34,30.94 42.26,33.02 37,33.02 36.48,33.54 36.48,34.79 35.54,35.74 35.54,39.71 36.03,40.2 v1(36.03,46.29)
CONF1: length 67.7
  TOP w0.203: U6.17 43.51,28.28 44.04,28.82 v1(44.33,28.82)
  TOP w0.229: R5.2 32.63,45.88 33.16,46.41 33.16,48 33.6,48.43 v1(34.39,48.43) 53.74,48.43 54.83,49.52 54.83,57.14 52.13,59.84 JMP7.2
  L4_SIG w0.152: v1(34.39,48.43) 34.39,45.88 33.43,44.92 33.43,41.01 34.91,39.52 34.91,35.8 36.11,34.61 36.11,33.3 36.74,32.67 41.27,32.67 42.48,31.46 42.48,30.67 v1(44.33,28.82)
CONF2: length 62.5
  TOP w0.203: 44.06,27.51 43.91,27.35 U6.16
  TOP w0.229: JMP8.2 49.66,49.17 v1(32.41,49.17) 28.28,49.17 27.42,48.31 27.42,46.11 27.65,45.88 R1.1 ; v1(44.06,27.97) 44.06,27.51
  L4_SIG w0.152: v1(44.06,27.97) 44.06,28.35 40.11,32.31 34.48,32.31 31.76,35.03 31.76,39.37 32.88,40.5 32.88,48.7 v1(32.41,49.17)
DM: length 80
  TOP w0.203: v2(50.55,40) P1.B7 ; U6.53 43.11,19.81 arc(43.04,19.48) 42.86,19.21 arc(42.73,18.9) 42.86,18.59 v1(42.96,18.49) ; P1.A7 v2(48.88,40.75) arc(48.79,40.69) 48.68,40.67 48.11,40.67 arc(47.74,40.6) 47.42,40.38 46.54,39.5 arc(45.99,39.13) 45.33,39 44.96,39 arc(44.91,39.01) 44.88,39.03 arc(44.84,39.06) 44.8,39.07 U4.2 U4.9 43.23,39.07 arc(43.19,39.06) 43.15,39.03 arc(43.11,39.01) 43.07,39 42.71,39 arc(42.43,39.12) 42.31,39.4 42.31,39.73 arc(42.33,39.81) 42.37,39.87 v1(42.5,40)
  BOTTOM w0.203: P2.2 4.89,18.51 arc(4.96,18.52) 5.03,18.57 5.05,18.59 arc(5.12,18.63) 5.19,18.65 6.37,18.65 arc(6.53,18.62) 6.66,18.53 7.35,17.85 arc(8.62,16.94) 10.12,16.51 arc(10.24,16.5) 10.36,16.49 17.7,16.49 arc(18.36,16.36) 18.91,15.99 arc(19.8,15.4) 20.84,15.19 32.26,15.19 arc(33.12,15.36) 33.86,15.85 34.47,16.47 arc(34.75,16.66) 35.09,16.72 41.8,16.72 arc(42.36,16.9) 42.71,17.37 arc(42.75,17.53) 42.76,17.69 42.76,18.02 arc(42.81,18.27) v1(42.96,18.49) arc(42.84,18.67) 42.8,18.87 42.8,19.14 arc(42.91,19.4) 43.16,19.51 43.83,19.51 arc(44.48,19.63) 45.05,19.97 arc(45.05,19.97) 45.05,19.97 45.06,19.97 arc(45.3,20.33) 45.38,20.75 45.38,26.71 arc(45.42,27.08) 45.53,27.43 45.54,27.45 45.55,27.48 arc(45.63,27.69) 45.65,27.92 45.65,29.88 arc(45.41,31.08) 44.73,32.09 42.79,34.04 arc(42.44,34.56) 42.31,35.19 42.31,38.19 arc(42.37,38.34) 42.52,38.39 arc(42.72,38.6) 42.52,38.8 arc(42.37,38.86) 42.31,39 arc(42.31,39.01) 42.31,39.01 42.31,39.55 arc(42.36,39.8) v1(42.5,40) ; v2(48.88,40.75) 48.88,40.74 49.42,40.74 50.17,40 v2(50.55,40)
DP: length 79.1
  TOP w0.203: v1(41.74,40) 41.87,39.87 arc(41.91,39.81) 41.93,39.73 41.93,39.41 arc(42.16,38.86) 42.7,38.63 43.07,38.63 arc(43.11,38.62) 43.15,38.6 43.15,38.6 arc(43.19,38.57) 43.23,38.57 U4.10 U4.1 44.8,38.57 arc(44.84,38.57) 44.88,38.6 44.88,38.6 arc(44.91,38.62) 44.95,38.63 45.33,38.63 arc(46.13,38.79) 46.8,39.24 47.68,40.12 arc(47.88,40.25) 48.11,40.3 49.48,40.3 arc(49.55,40.29) P1.A6 50.1,40.25 arc(50.18,40.26) 50.24,40.31 50.36,40.42 arc(50.44,40.48) 50.54,40.5 P1.B6 ; v1(42.19,18.49) 42.22,18.52 arc(42.33,18.67) 42.36,18.85 arc(42.36,18.9) 42.35,18.95 42.34,19.03 arc(42.31,19.11) 42.25,19.18 42.07,19.36 arc(41.95,19.55) 41.91,19.77 U6.50
  BOTTOM w0.203: P2.3 4.89,19.16 arc(4.96,19.14) 5.03,19.1 5.05,19.08 arc(5.12,19.03) 5.19,19.02 5.31,19.02 arc(5.45,19.08) 5.51,19.22 arc(5.72,19.42) 5.92,19.22 arc(5.98,19.08) 6.12,19.02 6.37,19.02 arc(6.67,18.96) 6.93,18.79 7.61,18.11 arc(8.78,17.28) 10.15,16.87 arc(10.26,16.87) 10.36,16.86 17.7,16.86 arc(18.5,16.7) 19.17,16.25 arc(19.94,15.74) 20.84,15.56 32.26,15.56 arc(32.98,15.71) 33.59,16.12 34.21,16.73 arc(34.61,17) 35.09,17.09 41.81,17.09 arc(42.14,17.2) 42.36,17.49 arc(42.38,17.59) 42.39,17.69 42.39,18.02 arc(42.34,18.27) v1(42.19,18.49) 42.28,18.58 arc(42.39,18.74) 42.43,18.94 42.43,19.14 arc(42.64,19.66) 43.16,19.87 43.83,19.87 arc(44.34,19.97) 44.79,20.23 44.8,20.23 arc(44.96,20.47) 45.01,20.75 45.01,26.71 arc(45.06,27.15) 45.2,27.58 45.22,27.63 arc(45.27,27.77) 45.28,27.92 45.28,29.88 arc(45.07,30.94) 44.47,31.83 42.53,33.78 arc(42.1,34.42) 41.94,35.19 41.94,39.51 arc(41.89,39.78) v1(41.74,40)
DP0N: length 18
  TOP w0.152: U1.40 arc(28.88,41.56) 28.89,41.61 28.89,41.93 arc(28.89,41.97) 28.88,42.01 arc(28.88,42.01) 28.88,42.02 arc(28.83,42.15) 28.75,42.26 26.72,44.29 arc(26.09,44.71) 25.35,44.85 19.98,44.85 arc(19.51,44.76) 19.12,44.5 18.53,43.9 arc(18.22,43.7) 17.86,43.63 16.66,43.63 arc(16.52,43.57) 16.47,43.43 16.47,43.42 arc(16.4,43.27) 16.25,43.2 16.22,43.2 arc(16.07,43.27) 16.01,43.42 16.01,43.43 arc(15.95,43.57) 15.81,43.63 arc(15.81,43.63) 15.81,43.63 15.79,43.63 arc(15.71,43.61) 15.63,43.58 15.62,43.57 arc(15.54,43.52) 15.46,43.46 arc(15.42,43.44) 15.39,43.41 arc(15.34,43.37) 15.29,43.34 15.26,43.32 arc(15.19,43.3) 15.11,43.29 13.56,43.29 arc(13.56,43.29) P3.10
DP0P: length 18
  TOP w0.152: P3.12 15.04,44.29 arc(15.26,44.24) 15.44,44.12 15.5,44.06 arc(15.64,43.97) 15.81,43.93 17.86,43.93 arc(18.1,43.98) 18.31,44.12 18.9,44.71 arc(19.4,45.04) 19.98,45.16 25.35,45.16 arc(26.21,44.99) 26.94,44.5 28.97,42.48 arc(29.1,42.3) 29.18,42.09 arc(29.19,42.01) 29.2,41.93 29.2,41.64 29.2,41.64 arc(29.21,41.58) U1.39
DP1N: length 18
  TOP w0.152: P3.7 15.06,41.79 arc(15.23,41.82) 15.39,41.91 arc(15.42,41.94) 15.46,41.97 arc(15.54,42.02) 15.62,42.07 15.63,42.08 arc(15.71,42.11) 15.79,42.13 arc(15.8,42.13) 15.8,42.13 20,42.13 arc(20.33,41.99) 20.46,41.67 20.46,41.17 arc(21.22,40.41) 21.98,41.17 21.98,41.67 arc(22.12,41.99) 22.44,42.13 22.55,42.13 arc(22.76,42.09) 22.94,41.97 24.18,40.72 arc(24.55,40.48) 24.98,40.39 28.3,40.39 U1.3
DP1P: length 18
  TOP w0.152: P3.9 15.06,42.79 arc(15.25,42.75) 15.41,42.64 15.5,42.55 arc(15.63,42.46) 15.79,42.43 arc(15.8,42.43) 15.81,42.43 20,42.43 arc(20.54,42.21) 20.76,41.67 20.76,41.17 arc(21.22,40.71) 21.68,41.17 21.68,41.67 arc(21.9,42.21) 22.44,42.43 22.55,42.43 arc(22.88,42.37) 23.16,42.18 24.4,40.94 arc(24.67,40.76) 24.98,40.7 28.25,40.7 arc(28.32,40.71) U1.2
DP2N: length 18
  TOP w0.152: P3.4 15.06,40.29 arc(15.23,40.32) 15.39,40.41 arc(15.42,40.44) 15.46,40.47 arc(15.54,40.52) 15.62,40.57 15.63,40.58 arc(15.71,40.61) 15.79,40.63 arc(15.8,40.63) 15.8,40.63 16.33,40.63 arc(16.68,40.48) 16.83,40.13 16.83,39.96 arc(17.05,39.42) 17.59,39.19 arc(18.12,39.41) 18.34,39.93 18.34,40.33 arc(18.46,40.64) 18.77,40.76 18.92,40.76 arc(19.13,40.68) 19.22,40.46 19.22,40.01 arc(19.46,39.43) 20.03,39.19 28.25,39.19 arc(28.32,39.18) U1.6
DP2P: length 18
  TOP w0.152: P3.6 15.06,41.29 arc(15.25,41.25) 15.41,41.14 15.5,41.05 arc(15.63,40.96) 15.79,40.93 arc(15.8,40.93) 15.81,40.93 16.33,40.93 arc(16.9,40.7) 17.13,40.13 17.13,39.96 arc(17.27,39.63) 17.59,39.5 arc(17.9,39.63) 18.03,39.93 18.03,40.33 arc(18.25,40.85) 18.77,41.07 18.92,41.07 arc(19.35,40.89) 19.52,40.46 19.52,40.01 arc(19.67,39.65) 20.03,39.5 28.25,39.5 arc(28.32,39.51) U1.5
DP3N: length 18
  TOP w0.152: P3.1 15.06,38.79 arc(15.23,38.82) 15.39,38.91 arc(15.51,39) 15.63,39.08 arc(15.72,39.11) 15.81,39.13 15.85,39.13 arc(16.08,39.03) 16.17,38.81 16.17,37.97 arc(16.45,37.3) 17.12,37.02 18.47,37.02 arc(19.01,37.24) 19.23,37.78 arc(19.26,37.9) 19.34,37.98 19.4,38.02 arc(19.47,38.06) 19.55,38.07 19.83,38.07 arc(19.91,38.06) 19.98,38.02 20.04,37.99 arc(20.12,37.9) 20.15,37.78 arc(20.39,37.2) 20.97,36.96 22.28,36.96 arc(22.95,37.09) 23.52,37.47 arc(24.09,37.86) 24.77,37.99 27.9,37.99 arc(27.93,37.99) 27.96,37.97 27.96,37.97 arc(27.99,37.95) 28.02,37.95 U1.9
DP3P: length 18
  TOP w0.152: P3.3 15.06,39.79 arc(15.25,39.75) 15.41,39.64 15.48,39.57 arc(15.63,39.47) 15.82,39.43 15.85,39.43 arc(16.29,39.25) 16.47,38.81 16.47,37.97 arc(16.66,37.51) 17.12,37.32 18.47,37.32 arc(18.79,37.46) 18.93,37.78 arc(18.99,38.04) 19.17,38.24 19.23,38.28 arc(19.38,38.35) 19.55,38.37 19.83,38.37 arc(19.99,38.35) 20.13,38.29 20.19,38.25 20.21,38.24 arc(20.39,38.04) 20.45,37.78 arc(20.6,37.41) 20.97,37.26 22.28,37.26 arc(22.83,37.37) 23.3,37.69 arc(23.98,38.14) 24.77,38.3 27.9,38.3 arc(27.93,38.3) 27.96,38.32 arc(27.99,38.34) 28.02,38.35 U1.8
HPDIN: length 61
  TOP w0.203: U6.30 37.88,25.63 37.41,26.11 ; R22.1 v1(1.51,54.05)
  TOP w0.229: v1(32.73,29.29) 35.73,29.29 35.91,29.12 35.91,28.83 37.41,27.33 37.41,26.11 ; P3.18 v1(16.11,47.29)
  L4_SIG w0.152: v1(1.51,54.05) 1.51,51.69 5.92,47.29 v1(16.11,47.29) 16.11,37.44 25.49,28.05 31.49,28.05 v1(32.73,29.29)
I2C2_SCL: length 4.4
  TOP w0.203: 36.39,26.22 36.39,25.85 37.4,24.83 U6.32
  TOP w0.229: 36.39,26.22 36.39,26.38 R53.2
I2C2_SDA: length 3.8
  TOP w0.203: U6.33 37.11,24.43 36.29,25.25
  TOP w0.229: 36.29,25.25 36.29,25.26 R54.2
LDO_3V3: length 14.5
  TOP w0.203: v1(45.95,23.66) 45.58,24.03 U6.9
  TOP w0.254: R54.1 v1(33.76,26.22) ; R52.1 v1(33.76,25) ; v1(40.56,31.12) 40.69,30.99 R58.1 ; R53.1 v1(33.76,27.44) ; R57.1 v1(36.98,31.09) ; R56.1 v1(33.76,29.93)
  TOP w0.381: R68.1 v3(40.49,14.88) ; U10.8 C15.1 v3(37.66,12.22) ; R66.1 v3(42.32,14.57) ; R65.1 v3(40.48,2.11) ; R64.1 v3(39.21,2.11) ; R67.2 v3(41.75,2.11)
  BOTTOM w0.254: v1(47.69,22.95) 47.68,22.96 v1(47.08,22.96) 46.93,22.96 46.74,23.15 C14.1 45.95,23.66 v1(45.95,23.66)
  BOTTOM w0.381: R40.1 v1(51,21.45) ; R41.1 v1(52.49,23.77)
MISO: length 14.8
  TOP w0.229: U7.18 19.58,21.47 19.82,21.23 19.82,15.88 20.44,15.25 23.23,15.25 P4.5
MODE0: length 11.4
  TOP w0.203: R30.1 v1(19.19,43.58)
  BOTTOM w0.229: v1(19.19,43.58) 20.89,45.28 20.89,51.12 JMP3.2
MODE1: length 25.7
  TOP w0.229: R31.1 25.28,30.82 22.67,33.43 v1(22.67,34.04)
  BOTTOM w0.229: v1(22.67,34.04) 22.67,48.86 JMP2.2
MOSI: length 21.9
  TOP w0.229: U7.3 v1(10.48,21.47)
  L4_SIG w0.152: P4.8 22.99,10.16 21.81,8.99 19.78,8.99 18.52,10.24 18.52,11.42 11.86,18.08 11.86,20.66 11.05,21.47 v1(10.48,21.47)
MUX_SCL: length 61.3
  TOP w0.229: v1(30.4,21.44) 29.78,20.82 U8.17 ; v1(13.88,19.17) 13.88,17.95 13.5,17.57 U7.9 ; R63.2 v1(39.45,31.09) ; R6.2 v1(31.88,47.82)
  L4_SIG w0.152: v1(31.88,47.82) 31.35,47.3 31.35,34.82 34.23,31.94 38.6,31.94 v1(39.45,31.09) 38.74,30.38 38.74,28.91 34.27,24.44 33.39,24.44 v1(30.4,21.44) 26.31,21.44 25.32,20.45 19.2,20.45 17.92,19.17 v1(13.88,19.17)
MUX_SDA: length 51.6
  TOP w0.229: R59.2 v1(38.24,31.09) ; R2.1 v1(28.2,47.92) ; U8.4 23.88,20.82 24.09,21.03 v1(24.83,21.03) 24.83,17.77 24.62,17.57 U8.9
  L4_SIG w0.152: v1(24.83,21.03) 25.9,22.1 30.03,22.1 33.59,25.66 34.36,25.66 38.24,29.53 v1(38.24,31.09) 37.73,31.6 34.05,31.6 30.96,34.69 30.96,47.34 30.38,47.92 v1(28.2,47.92)
PAD1: length 2.9
  TOP w0.203: U6.15 44.31,26.09 v1(44.15,25.93) ; U6.19 42.71,26.23 v1(43.01,25.93) ; U6.8 44.42,23.63 v1(44.15,23.9)
  vias: v1(43.01,24.92) v1(43.01,23.9) v1(43.58,25.43) v1(43.58,24.41) v1(44.15,24.92)
PAD2: length 3
  TOP w0.203: v1(44.15,23.01) 44.38,23.23 U6.7 ; U6.56 44.31,20.82 v1(44.15,20.98) ; U6.52 42.71,20.68 v1(43.01,20.98)
  vias: v1(43.01,23.01) v1(43.01,21.99) v1(43.58,22.5) v1(43.58,21.48) v1(44.15,21.99)
RX1N: length 23.7
  TOP w0.203: P1.B10 v2(50.55,38.5) ; U1.24 31.72,37.14 31.74,37.16 32.02,37.16 arc(32.17,37.13) 32.29,37.05 32.4,36.94 33.25,36.09 arc(33.62,35.85) 34.05,35.76 39.26,35.76 arc(39.3,35.75) 39.34,35.73 arc(39.38,35.7) 39.42,35.69 U2.5 U2.6 40.99,35.69 arc(41.03,35.7) 41.07,35.73 arc(41.1,35.75) 41.14,35.76 43.43,35.76 arc(43.78,35.62) 43.92,35.27 43.92,35.24 arc(43.87,34.98) v1(43.73,34.77)
  BOTTOM w0.203: v1(43.73,34.77) 43.86,34.9 arc(43.91,34.97) 43.93,35.06 43.93,35.76 arc(43.93,35.9) 43.96,36.04 arc(44.11,36.43) 44.36,36.77 45.51,37.92 arc(46.08,38.3) 46.74,38.43 50.39,38.43 arc(50.48,38.45) v2(50.55,38.5)
RX1P: length 23.7
  TOP w0.203: P1.B11 v2(50.55,38) ; U1.25 31.72,37.55 31.74,37.53 32.02,37.53 arc(32.31,37.47) 32.55,37.31 32.66,37.2 33.51,36.35 arc(33.76,36.19) 34.05,36.13 39.26,36.13 arc(39.3,36.14) 39.34,36.16 arc(39.38,36.19) 39.42,36.19 U2.4 U2.7 40.99,36.19 arc(41.03,36.19) 41.07,36.16 arc(41.1,36.14) 41.15,36.13 43.43,36.13 arc(44.04,35.88) 44.29,35.27 44.29,35.24 arc(44.34,34.98) v1(44.49,34.77)
  BOTTOM w0.203: v1(44.49,34.77) 44.36,34.9 arc(44.31,34.96) 44.3,35.04 arc(44.3,35.04) 44.3,35.04 arc(44.3,35.05) 44.3,35.06 44.3,35.76 arc(44.3,35.86) 44.32,35.96 arc(44.43,36.26) 44.62,36.51 45.77,37.66 arc(46.22,37.96) 46.74,38.06 50.4,38.06 arc(50.48,38.05) v2(50.55,38)
RX2N: length 23.7
  TOP w0.203: P1.A10 49.04,42.25 arc(48.99,42.26) 48.96,42.28 arc(48.92,42.31) 48.88,42.31 48.19,42.31 arc(47.26,42.7) 46.88,43.62 46.88,44.4 arc(46.78,44.89) 46.48,45.3 arc(45.93,45.7) 45.26,45.84 41.14,45.84 41.07,45.76 arc(41.03,45.74) 40.99,45.73 U3.4 U3.7 39.42,45.73 arc(39.38,45.74) 39.34,45.76 arc(39.3,45.79) 39.26,45.79 38.09,45.79 arc(37.7,45.72) 37.37,45.5 36.94,45.06 arc(36.46,44.74) 35.88,44.63 33.97,44.63 arc(33.61,44.56) 33.31,44.35 32.67,43.71 arc(32.58,43.58) 32.55,43.43 32.55,42.07 arc(32.47,41.69) 32.26,41.36 31.64,40.74 U1.33
RX2P: length 23.6
  TOP w0.203: P1.A11 49.58,42.77 49.09,42.77 arc(49.02,42.76) 48.96,42.72 arc(48.92,42.69) 48.88,42.68 48.19,42.68 arc(47.52,42.96) 47.25,43.62 47.25,44.4 arc(47.12,45.03) 46.74,45.56 arc(46.07,46.04) 45.26,46.21 41.05,46.21 arc(41.02,46.22) 40.99,46.23 U3.5 40.55,46.27 39.86,46.27 U3.6 39.42,46.23 arc(39.38,46.22) 39.34,46.19 arc(39.3,46.17) 39.26,46.16 38.09,46.16 arc(37.56,46.06) 37.11,45.76 36.68,45.33 arc(36.31,45.08) 35.89,45 33.97,45 arc(33.47,44.9) 33.05,44.62 32.41,43.97 arc(32.24,43.72) 32.18,43.43 32.18,42.07 arc(32.13,41.83) 32,41.62 31.52,41.14 U1.34
SBU1: length 25.2
  TOP w0.229: v1(42.56,41.86) 42.91,41.86 43.14,42.09 43.61,42.09 U5.4 U5.7 44.77,42.11 45.02,41.86 45.69,41.86 46.3,41.25 49.6,41.25 P1.A8 ; v1(37.3,34.97) R7.1 35.84,34.29 35.12,35.01 32.6,35.01 32.08,35.53 32.08,35.89 31.63,36.35 U1.22
  L4_SIG w0.152: v1(42.56,41.86) 41.07,41.86 39.94,40.73 39.94,39.15 37.3,36.52 v1(37.3,34.97)
SBU2: length 29.4
  TOP w0.203: U5.5 U5.6
  TOP w0.229: U5.6 44.55,41.61 44.94,41.22 v1(45.3,41.22) ; P1.B8 v2(50.48,39.5) ; v1(43.01,41.26) 43.36,41.61 U5.5 ; v1(37.32,33.56) R8.1 36.69,32.28 34.07,32.28 31.63,34.73 31.63,35.72 31.4,35.95 U1.21
  L4_SIG w0.152: v1(43.01,41.26) 41.07,41.26 40.4,40.58 40.4,38.96 37.85,36.42 37.85,34.09 v1(37.32,33.56)
  BOTTOM w0.229: v2(50.48,39.5) 49.82,39.5 49.07,40.25 46.26,40.25 v1(45.3,41.22)
SCL: length 12.6
  TOP w0.229: U8.18 26.43,21.47 26.1,21.14 26.1,17.46 P4.1
SDA: length 15.8
  TOP w0.229: U8.3 22.91,21.46 21.42,21.46 20.63,20.67 20.63,16.36 20.95,16.04 24.98,16.04 P4.3
SDA_GND: length 10.6
  TOP w0.229: v1(21.45,18.1) 21.57,18.22 U8.8
  L4_SIG w0.152: v1(21.45,18.1) 19.23,15.87 19.23,11.64 P4.10
SPI_CLK: length 38
  TOP w0.203: v1(36.14,22.14) 36.43,22.43 U6.38
  TOP w0.229: U10.6 v1(41.75,12.78) ; U7.14 18.44,18.87 v1(19.05,19.48)
  L4_SIG w0.152: v1(36.14,22.14) 36.51,22.51 37.34,22.51 37.66,22.19 37.66,15.1 39.99,12.78 v1(41.75,12.78)
  BOTTOM w0.229: v1(36.14,22.14) 35.55,21.55 34.65,21.55 34.2,22.01 21.58,22.01 v1(19.05,19.48)
SPI_MISO: length 67.2
  TOP w0.203: v1(35.23,23.03) 35.23,23.03 35.43,23.23 U6.36
  TOP w0.229: U7.17 15.29,20.82 14.92,20.45 14.92,16.15 17.9,13.17 17.9,10.93 21.28,7.55 40.25,7.55 40.48,7.32 U10.2 v1(40.48,4.66) R65.2
  L4_SIG w0.152: v1(35.23,23.03) 34.56,22.36 34.56,21.28 36.32,19.53 36.32,6.53 38.83,4.02 39.84,4.02 v1(40.48,4.66)
SPI_MOSI: length 48.6
  TOP w0.203: 43.02,13.03 v1(43.01,13.04) ; 35.65,22.56 35.93,22.83 U6.37
  TOP w0.229: U7.4 v1(10.47,20.82) ; v1(43.01,13.04) R66.2 ; 35.65,22.56 v1(35.23,22.14) ; U10.5 43.02,13.03
  L4_SIG w0.152: v1(43.01,13.04) 42.24,13.81 40.44,13.81 38.72,15.53 38.72,16.24 38.21,16.75 38.21,22.43 37.7,22.94 36.03,22.94 v1(35.23,22.14)
  BOTTOM w0.229: v1(35.23,22.14) 34.6,22.76 13.38,22.76 11.44,20.82 v1(10.47,20.82)
SPI_SS: length 51.9
  TOP w0.203: v1(36.97,21.84) 37.16,22.03 U6.39
  TOP w0.229: R64.2 v1(39.21,4.66) U10.1 ; U7.7 v1(10.47,18.87)
  L4_SIG w0.152: v1(36.97,21.84) 36.97,6.9 v1(39.21,4.66)
  BOTTOM w0.229: v1(36.97,21.84) 34.62,19.49 31.49,19.49 30.86,18.86 15.34,18.86 14.3,19.9 12.01,19.9 10.98,18.87 v1(10.47,18.87)
SS: length 11.6
  TOP w0.229: v1(18.46,13.02) 18.53,12.95 P4.9 ; v1(13.01,18.75) 13.01,18.45 12.78,18.22 U7.8
  L4_SIG w0.152: v1(18.46,13.02) 13.01,18.47 v1(13.01,18.75)
SSRXN: length 22.1
  TOP w0.203: C4.1 22.48,35.11 arc(22.32,35.21) 22.13,35.25 20.73,35.25 arc(20.11,35.13) 19.59,34.78 12.07,27.26 arc(11.4,26.81) 10.6,26.65 6.26,26.65 arc(6.13,26.64) 6.02,26.6 arc(5.89,26.54) v1(5.78,26.45)
  BOTTOM w0.203: v1(5.78,26.45) 5.64,26.59 5.57,26.64 arc(5.54,26.65) 5.51,26.65 arc(5.5,26.65) 5.5,26.65 arc(5.5,26.65) 5.5,26.65 5.21,26.65 arc(5.2,26.65) 5.2,26.65 arc(5.17,26.65) 5.15,26.64 arc(5.1,26.62) 5.05,26.59 5.03,26.57 arc(4.96,26.52) 4.89,26.51 P2.9
SSRXP: length 22.1
  TOP w0.203: C3.1 22.48,35.76 arc(22.32,35.65) 22.13,35.62 20.73,35.62 arc(19.97,35.47) 19.33,35.04 11.81,27.52 arc(11.26,27.15) 10.6,27.02 6.26,27.02 arc(6,27.07) v1(5.78,27.21)
  BOTTOM w0.203: v1(5.78,27.21) 5.65,27.08 5.57,27.03 arc(5.54,27.02) 5.5,27.02 arc(5.5,27.02) 5.5,27.02 5.21,27.02 arc(5.19,27.02) 5.18,27.02 arc(5.11,27.04) 5.05,27.08 5.03,27.1 arc(4.96,27.14) 4.89,27.16 P2.10
SSTXN: length 29.1
  TOP w0.203: v1(7.02,25.26) 7.02,25.38 arc(7.05,25.51) 7.13,25.62 7.14,25.63 arc(7.26,25.72) 7.41,25.75 7.41,25.75 arc(7.71,25.67) 7.88,25.41 arc(8.03,25.16) 8.31,25.07 23.19,25.07 arc(23.33,25.07) 23.47,25.08 arc(24.84,25.43) 26.01,26.24 28.06,28.28 arc(28.72,29.27) 28.95,30.44 28.95,30.75 arc(28.9,31.03) C1.1
  BOTTOM w0.203: P2.7 4.89,25.21 arc(4.96,25.19) 5.03,25.15 5.05,25.13 arc(5.11,25.09) 5.18,25.07 arc(5.19,25.07) 5.2,25.07 6.74,25.07 arc(6.74,25.07) 6.74,25.07 arc(6.78,25.07) 6.81,25.08 6.89,25.13 v1(7.02,25.26)
SSTXP: length 29.1
  TOP w0.203: v1(7.02,24.5) arc(7.24,24.65) 7.5,24.7 23.19,24.7 arc(23.34,24.7) 23.49,24.71 arc(25,25.09) 26.27,25.97 28.32,28.02 arc(29.06,29.13) 29.32,30.44 29.32,30.75 arc(29.38,31.03) C2.1
  BOTTOM w0.203: v1(7.02,24.5) 6.89,24.64 6.81,24.69 arc(6.78,24.7) 6.74,24.7 5.2,24.7 arc(5.18,24.7) 5.15,24.69 arc(5.1,24.67) 5.05,24.64 5.03,24.62 arc(4.96,24.57) 4.89,24.56 P2.6
SYS_5V:
  vias: v1(15.54,20.18) v1(16.18,20.18) v1(26.71,20.18) v1(27.35,20.18) v3(14.26,11.67) v3(14.26,10.91) v3(15.02,11.67) v3(15.02,10.91) v3(15.78,11.67) v3(15.78,10.91) v3(16.54,11.67) v3(16.54,10.91) v3(17.3,11.67) v3(17.3,10.91) v3(27.92,61.98) v3(27.92,61.34) v3(27.92,60.71) v3(27.92,60.07) v3(28.56,61.98) v3(28.56,61.34) v3(28.56,60.71) v3(28.56,60.07) v3(29.19,61.98) v3(29.19,61.34) v3(29.19,60.71) v3(29.19,60.07) v3(39.48,61.98) v3(39.48,61.34) v3(39.48,60.71) v3(39.48,60.07) v3(40.11,61.98) v3(40.11,61.34) v3(40.11,60.71) v3(40.11,60.07) v3(40.75,61.98) v3(40.75,61.34) v3(40.75,60.71) v3(40.75,60.07)
TX1N: length 23.7
  TOP w0.203: P1.A3 49.04,38.75 arc(48.99,38.74) 48.96,38.72 arc(48.92,38.69) 48.88,38.68 48.49,38.68 arc(48.02,38.59) 47.62,38.32 arc(46.85,37.81) 45.94,37.63 41.15,37.63 arc(41.1,37.64) 41.07,37.66 arc(41.03,37.69) 40.99,37.69 U2.10 U2.1 39.42,37.69 arc(39.38,37.69) 39.34,37.66 arc(39.3,37.64) 39.26,37.63 38.88,37.63 arc(38.65,37.67) 38.45,37.81 arc(38.38,37.9) 38.36,38.02 38.36,40.02 arc(38.38,40.1) 38.42,40.17 v1(38.56,40.31) ; U1.27 31.72,38.35 31.74,38.36 32.86,38.36 arc(33.13,38.31) v1(33.35,38.16)
  BOTTOM w0.203: v1(33.35,38.16) arc(33.57,38.3) 33.83,38.35 34.48,38.35 arc(34.84,38.28) 35.14,38.08 arc(35.59,37.78) 36.12,37.68 37.23,37.68 arc(38.03,38.01) 38.37,38.81 38.37,39.83 arc(38.42,40.09) v1(38.56,40.31)
TX1P: length 23.7
  TOP w0.203: P1.A2 49.04,38.25 arc(48.99,38.26) 48.96,38.28 arc(48.92,38.31) 48.88,38.31 48.49,38.31 arc(48.16,38.25) 47.88,38.06 arc(46.99,37.47) 45.94,37.26 41.14,37.26 arc(41.1,37.25) 41.07,37.23 arc(41.03,37.2) 40.99,37.19 U2.9 U2.2 39.42,37.19 arc(39.38,37.2) 39.34,37.23 arc(39.3,37.25) 39.26,37.26 38.88,37.26 arc(38.51,37.33) 38.19,37.54 arc(38.04,37.76) 37.99,38.02 37.99,39.49 arc(37.99,39.49) 37.99,39.5 37.99,40.03 arc(37.98,40.11) 37.93,40.17 v1(37.8,40.31) ; U1.28 31.72,38.74 31.74,38.73 32.9,38.73 arc(33.14,38.78) 33.35,38.92 v1(33.35,38.92)
  BOTTOM w0.203: v1(37.8,40.31) arc(37.95,40.09) 38,39.83 38,38.81 arc(37.77,38.27) 37.23,38.04 36.12,38.04 arc(35.73,38.12) 35.41,38.34 arc(34.98,38.62) 34.48,38.72 33.83,38.72 arc(33.57,38.77) v1(33.35,38.92)
TX2N: length 23.7
  TOP w0.203: v1(42.08,44.09) 42.08,44.09 arc(41.86,44.24) 41.6,44.29 41.14,44.29 arc(41.1,44.29) 41.07,44.26 arc(41.03,44.24) 40.99,44.23 U3.1 U3.10 39.42,44.23 arc(39.38,44.24) 39.34,44.26 39.34,44.26 arc(39.3,44.29) 39.26,44.29 38.41,44.29 arc(37.73,44.01) 37.44,43.32 37.44,42.42 arc(37.33,41.85) 37.01,41.36 36.05,40.41 arc(35.74,40.16) 35.38,40 arc(35.23,39.96) 35.08,39.95 33.04,39.95 arc(32.79,39.9) 32.56,39.77 arc(32.54,39.76) 32.53,39.74 arc(32.31,39.6) 32.06,39.55 31.33,39.55 U1.30 ; P1.B3 v2(50.55,42)
  BOTTOM w0.203: v2(50.55,42) arc(50.48,42.05) 50.39,42.06 49.54,42.06 arc(49.17,42.14) 48.85,42.35 47.4,43.8 arc(46.86,44.16) 46.22,44.29 42.56,44.29 arc(42.3,44.24) v1(42.08,44.09)
TX2P: length 23.7
  TOP w0.203: P1.B2 v2(50.55,42.5) ; U1.31 31.33,39.94 32.02,39.94 arc(32.18,39.97) 32.32,40.06 arc(32.66,40.25) 33.04,40.32 35.08,40.32 arc(35.18,40.33) 35.28,40.35 arc(35.55,40.48) 35.79,40.67 36.74,41.62 arc(36.99,41.99) 37.07,42.42 37.07,43.32 arc(37.47,44.27) 38.41,44.66 39.26,44.66 arc(39.3,44.67) 39.34,44.7 arc(39.38,44.72) 39.42,44.73 U3.9 U3.2 40.99,44.73 arc(41.03,44.72) 41.07,44.7 arc(41.1,44.67) 41.14,44.66 41.61,44.66 arc(41.87,44.71) v1(42.08,44.86)
  BOTTOM w0.203: v2(50.55,42.5) arc(50.48,42.45) 50.39,42.43 49.54,42.43 arc(49.31,42.48) 49.11,42.61 47.66,44.06 arc(47,44.5) 46.22,44.66 42.56,44.66 arc(42.3,44.71) v1(42.08,44.86)
N16768147: length 1.9
  BOTTOM w0.229: R9.1 12.31,11.13 D2.1
N16769233: length 12.3
  TOP w0.229: JMP1.1 12.35,55.7 15.4,52.65 15.4,49.05 14.64,48.29 P3.20
N16769682: length 5.8
  TOP w0.203: U1.36 30.45,41.85 30.98,42.38
  TOP w0.229: 30.98,42.38 R5.1 R6.1
